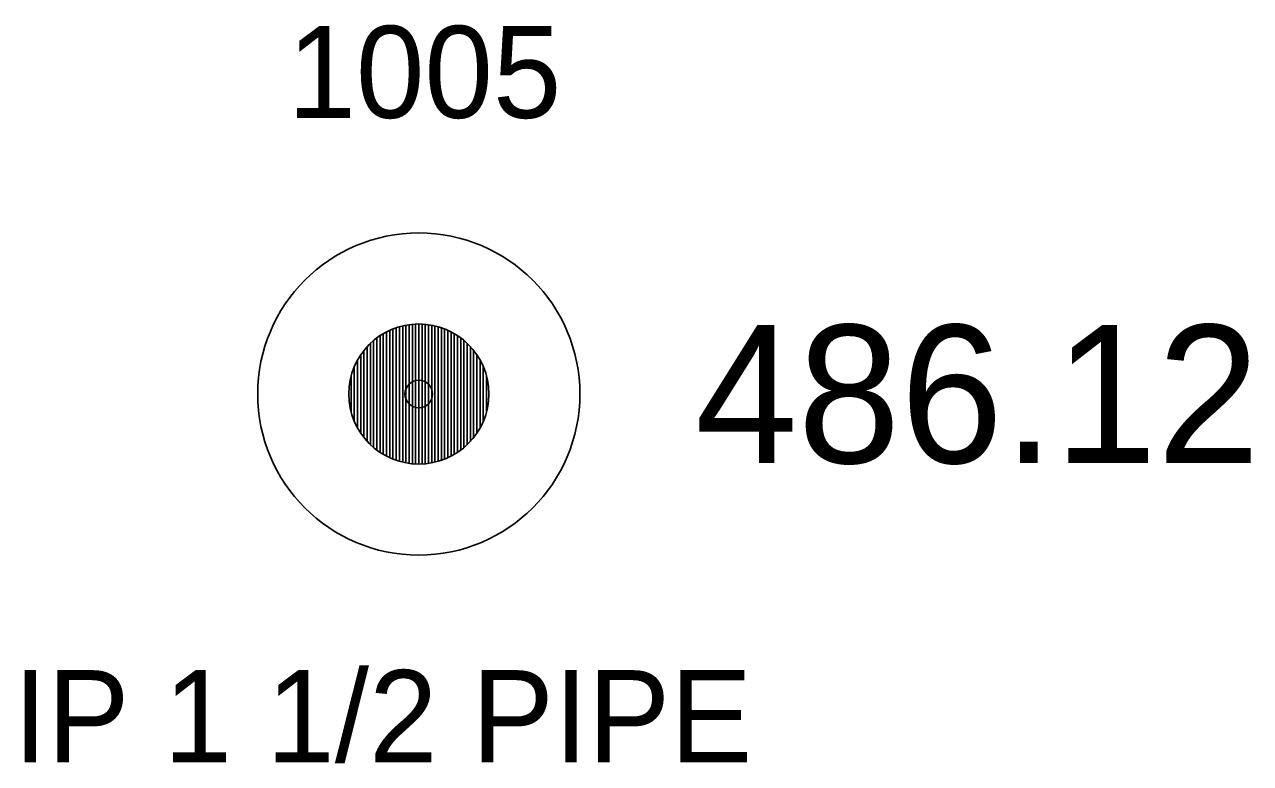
# Model space of a CAD drawing. Extents: x 1796360 to 1799195, y 895805 to 899730.
# Drawn here: x 1799045.14 to 1799058.45, y 899722.46 to 899730.49 of the extents above; entities that cross this region are included whole.
import ezdxf

# ---------------------------------------------------------------- set-up
doc = ezdxf.new("R2010")
doc.units = 0
for name, color, linetype in [('RD_EX_DV_Prop_txCode', 7, 'Continuous'), ('RD_EX_DV_PropPin', 7, 'Continuous'), ('RD_EX_TX_DV_Prop_ELEV', 7, 'Continuous'), ('RD_SMD_Locator', 7, 'Continuous')]:
    doc.layers.add(name, color=color, linetype=linetype)

msp = doc.modelspace()

# ---------------------------------------------------------------- linework, layer by layer
at = {"layer": 'RD_EX_DV_PropPin'}
for p, q in [((1799049.348, 899725.721), (1799049.348, 899727.237)), ((1799049.383, 899725.719), (1799049.383, 899727.239)), ((1799049.418, 899725.718), (1799049.418, 899727.24)), ((1799049.453, 899725.719), (1799049.453, 899727.239)), ((1799049.488, 899725.721), (1799049.488, 899727.237)), ((1799048.997, 899725.844), (1799048.997, 899727.114)), ((1799049.032, 899725.823), (1799049.032, 899727.135)), ((1799049.067, 899725.803), (1799049.067, 899727.155)), ((1799049.102, 899725.786), (1799049.102, 899727.172)), ((1799049.137, 899725.771), (1799049.137, 899727.187)), ((1799049.172, 899725.759), (1799049.172, 899727.199)), ((1799049.207, 899725.748), (1799049.207, 899727.21)), ((1799049.243, 899725.738), (1799049.243, 899727.22)), ((1799049.278, 899725.731), (1799049.278, 899727.227)), ((1799049.313, 899725.725), (1799049.313, 899727.233)), ((1799049.523, 899725.725), (1799049.523, 899727.233)), ((1799049.558, 899725.731), (1799049.558, 899727.227)), ((1799049.593, 899725.738), (1799049.593, 899727.22)), ((1799049.628, 899725.748), (1799049.628, 899727.21)), ((1799049.663, 899725.759), (1799049.663, 899727.199)), ((1799049.698, 899725.771), (1799049.698, 899727.187)), ((1799049.733, 899725.786), (1799049.733, 899727.172)), ((1799049.768, 899725.803), (1799049.768, 899727.155)), ((1799049.803, 899725.823), (1799049.803, 899727.135)), ((1799049.838, 899725.844), (1799049.838, 899727.114)), ((1799048.857, 899725.964), (1799048.857, 899726.994)), ((1799048.892, 899725.928), (1799048.892, 899727.03)), ((1799048.927, 899725.897), (1799048.927, 899727.061)), ((1799048.962, 899725.869), (1799048.962, 899727.089)), ((1799049.873, 899725.869), (1799049.873, 899727.089)), ((1799049.908, 899725.897), (1799049.908, 899727.061)), ((1799049.943, 899725.928), (1799049.943, 899727.03)), ((1799049.978, 899725.964), (1799049.978, 899726.994)), ((1799048.752, 899726.109), (1799048.752, 899726.849)), ((1799048.787, 899726.052), (1799048.787, 899726.906)), ((1799048.822, 899726.005), (1799048.822, 899726.953)), ((1799050.013, 899726.005), (1799050.013, 899726.953)), ((1799050.048, 899726.052), (1799050.048, 899726.906)), ((1799050.083, 899726.109), (1799050.083, 899726.849)), ((1799048.717, 899726.181), (1799048.717, 899726.777)), ((1799050.118, 899726.181), (1799050.118, 899726.777)), ((1799048.682, 899726.283), (1799048.682, 899726.675)), ((1799050.153, 899726.283), (1799050.153, 899726.675))]:
    msp.add_line(p, q, dxfattribs=at)
for radius in [1.75, 0.761]:
    msp.add_circle((1799049.418, 899726.479), radius, dxfattribs=at)
at = {"layer": 'RD_SMD_Locator'}
msp.add_circle((1799049.418, 899726.479), 0.15, dxfattribs=at)

# ---------------------------------------------------------------- texts
at = {"layer": 'RD_EX_DV_Prop_txCode'}
for s, p in [('1005', (1799047.992, 899729.479)), ('IP 1 1/2 PIPE', (1799045.012, 899722.479))]:
    msp.add_text(s, height=1, dxfattribs=at).set_placement(p)
at = {"layer": 'RD_EX_TX_DV_Prop_ELEV'}
msp.add_text('486.12', height=1.5, dxfattribs=at).set_placement((1799052.418, 899725.729))

doc.saveas('drawing.dxf')
